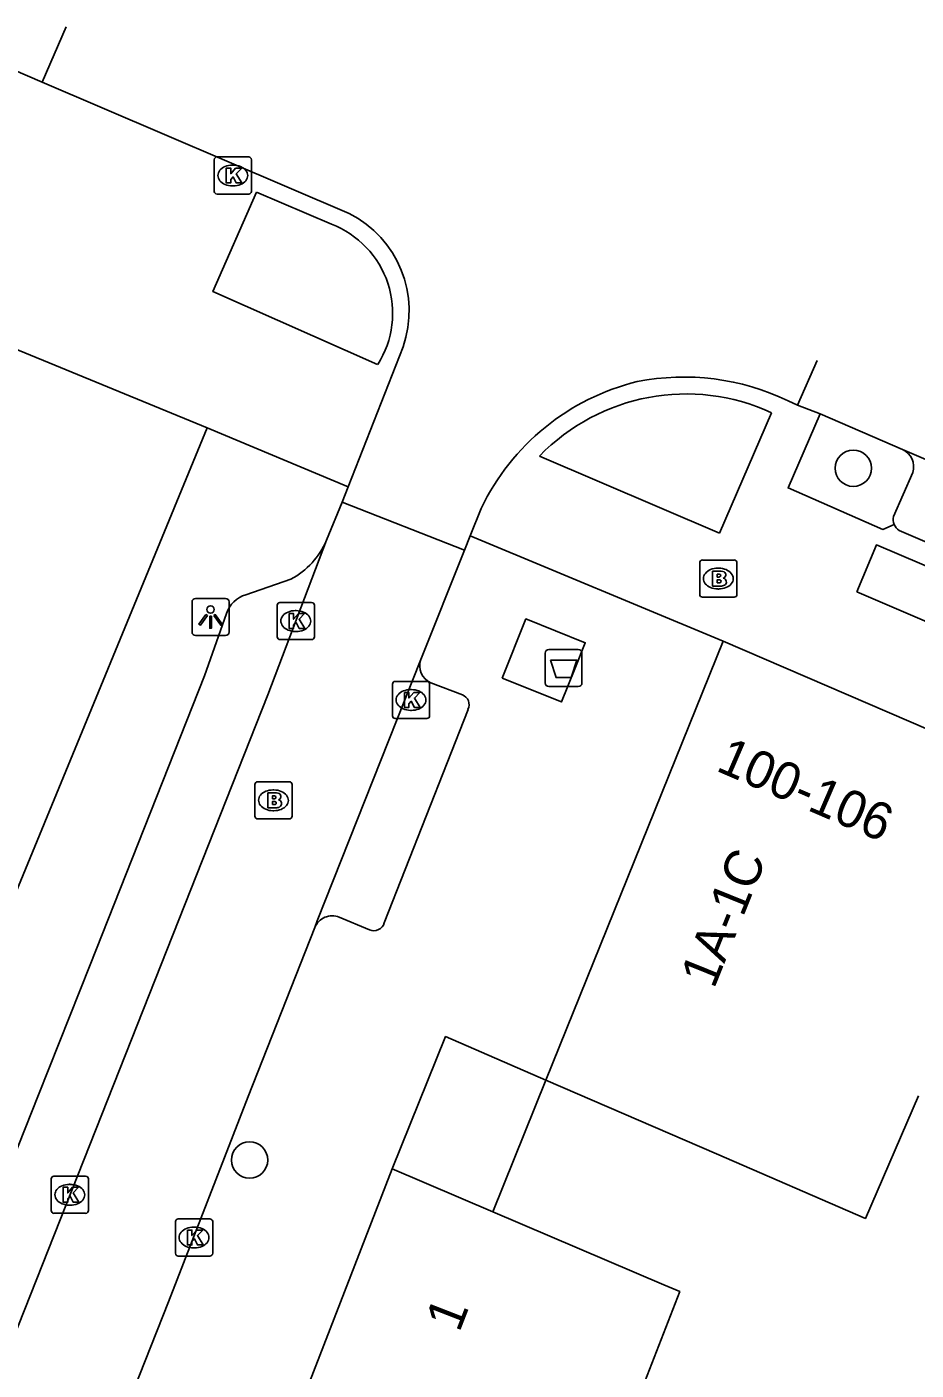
# Model space of a CAD drawing. Extents: x 161801 to 162379, y 382315 to 382832.
# Drawn here: x 162190.13 to 162214.04, y 382602.34 to 382638.48 of the extents above; entities that cross this region are included whole.
import ezdxf

# ---------------------------------------------------------------- set-up
doc = ezdxf.new("R2010")
doc.units = 0
for name, color, linetype in [('IMGEO_Afval_apart_plaats', 7, 'Continuous'), ('IMGEO_Boom', 7, 'Continuous'), ('IMGEO_Brandkraan', 7, 'Continuous'), ('IMGEO_Kolk', 7, 'Continuous'), ('IMGEO_Lichtpunt', 7, 'Continuous'), ('IMGEO_Pand', 7, 'Continuous'), ('IMGEO_Pand_nummerreeks', 7, 'Continuous'), ('IMGEO_Parkeervlak_open', 7, 'Continuous'), ('IMGEO_Rijbaan_lokaal_gesloten', 7, 'Continuous'), ('IMGEO_Rijbaan_lokaal_open', 7, 'Continuous'), ('IMGEO_Voetpad_gesloten', 7, 'Continuous'), ('IMGEO_Voetpad_open', 7, 'Continuous')]:
    doc.layers.add(name, color=color, linetype=linetype)

msp = doc.modelspace()

# ---------------------------------------------------------------- linework, layer by layer
at = {"layer": 'IMGEO_Afval_apart_plaats'}
for p, q in [((162204.167, 382621.733), (162204.957, 382621.733)), ((162204.957, 382621.733), (162204.167, 382621.733)), ((162204.067, 382620.833), (162204.067, 382621.633)), ((162204.067, 382621.633), (162204.067, 382620.833)), ((162205.057, 382621.633), (162205.057, 382620.833)), ((162205.057, 382620.833), (162205.057, 382621.633)), ((162204.957, 382620.733), (162204.167, 382620.733)), ((162204.167, 382620.733), (162204.957, 382620.733))]:
    msp.add_line(p, q, dxfattribs=at)
msp.add_lwpolyline([(162204.21, 382621.447), (162204.914, 382621.447), (162204.765, 382620.977), (162204.359, 382620.977), (162204.21, 382621.447)], dxfattribs=at)
for centre, start, end in [((162204.167, 382621.633), 90, 180), ((162204.167, 382621.633), 90, 180), ((162204.957, 382621.633), 0, 90), ((162204.957, 382621.633), 360, 90), ((162204.167, 382620.833), 180, 270), ((162204.167, 382620.833), 180, 270), ((162204.957, 382620.833), 270, 0), ((162204.957, 382620.833), 270, 0)]:
    msp.add_arc(centre, 0.1, start, end, dxfattribs=at)
at = {"layer": 'IMGEO_Boom'}
for centre in [(162212.353, 382626.609), (162196.117, 382607.996)]:
    msp.add_circle(centre, 0.489, dxfattribs=at)
at = {"layer": 'IMGEO_Brandkraan'}
for p, q in [((162208.222, 382623.213), (162208.222, 382624.065)), ((162208.297, 382624.139), (162209.149, 382624.139)), ((162208.71, 382623.919), (162208.735, 382623.919)), ((162209.223, 382624.065), (162209.223, 382623.213)), ((162208.733, 382623.359), (162208.708, 382623.359)), ((162209.149, 382623.139), (162208.297, 382623.139)), ((162196.334, 382618.174), (162197.186, 382618.174)), ((162196.259, 382617.248), (162196.259, 382618.1)), ((162196.747, 382617.954), (162196.772, 382617.954)), ((162197.26, 382618.1), (162197.26, 382617.248)), ((162196.77, 382617.394), (162196.745, 382617.394)), ((162197.186, 382617.174), (162196.334, 382617.174))]:
    msp.add_line(p, q, dxfattribs=at)
for points in [[(162208.222, 382623.213), (162208.222, 382624.065)], [(162208.297, 382624.139), (162209.149, 382624.139)], [(162209.223, 382624.065), (162209.223, 382623.213)], [(162208.57, 382623.839), (162208.57, 382623.439), (162208.783, 382623.439)], [(162208.801, 382623.839), (162208.57, 382623.839)], [(162208.749, 382623.758), (162208.695, 382623.758), (162208.695, 382623.682)], [(162208.695, 382623.682), (162208.748, 382623.682)], [(162208.757, 382623.606), (162208.695, 382623.606), (162208.695, 382623.525)], [(162208.695, 382623.525), (162208.757, 382623.525)], [(162209.149, 382623.139), (162208.297, 382623.139)], [(162196.334, 382618.174), (162197.186, 382618.174)], [(162196.259, 382617.248), (162196.259, 382618.1)], [(162196.607, 382617.874), (162196.607, 382617.474), (162196.82, 382617.474)], [(162196.838, 382617.874), (162196.607, 382617.874)], [(162196.786, 382617.793), (162196.732, 382617.793), (162196.732, 382617.717)], [(162197.26, 382618.1), (162197.26, 382617.248)], [(162196.732, 382617.717), (162196.785, 382617.717)], [(162196.794, 382617.641), (162196.732, 382617.641), (162196.732, 382617.56)], [(162196.732, 382617.56), (162196.794, 382617.56)], [(162197.186, 382617.174), (162196.334, 382617.174)]]:
    msp.add_lwpolyline(points, dxfattribs=at)
for centre, radius, start, end in [((162208.299, 382624.063), 0.0765, 91.552, 178.448), ((162208.299, 382624.063), 0.0765, 91.552, 178.448), ((162209.147, 382624.063), 0.0765, 1.552, 88.448), ((162209.147, 382624.063), 0.0765, 1.552, 88.448), ((162208.75, 382623.72), 0.0379, 267.8285, 90.9355), ((162208.758, 382623.565), 0.0404, 269.8759, 90.5077), ((162208.805, 382623.694), 0.145, 59.4692, 91.5367), ((162208.83, 382623.741), 0.0922, 285.5137, 58.1501), ((162208.835, 382623.549), 0.105, 301.3115, 78.989), ((162208.299, 382623.215), 0.0765, 181.552, 268.448), ((162208.299, 382623.215), 0.0765, 181.552, 268.448), ((162208.789, 382623.69), 0.251, 268.6676, 293.5347), ((162209.147, 382623.215), 0.0765, 271.552, 358.448), ((162209.147, 382623.215), 0.0765, 271.552, 358.448), ((162196.336, 382618.098), 0.0765, 91.552, 178.448), ((162196.336, 382618.098), 0.0765, 91.552, 178.448), ((162197.184, 382618.098), 0.0765, 1.552, 88.448), ((162197.184, 382618.098), 0.0765, 1.552, 88.448), ((162196.787, 382617.755), 0.0379, 267.8285, 90.9355), ((162196.842, 382617.729), 0.145, 59.4692, 91.5367), ((162196.867, 382617.776), 0.0922, 285.5137, 58.1501), ((162196.795, 382617.6), 0.0404, 269.8759, 90.5077), ((162196.826, 382617.725), 0.251, 268.6676, 293.5347), ((162196.872, 382617.584), 0.105, 301.3115, 78.989), ((162196.336, 382617.25), 0.0765, 181.552, 268.448), ((162196.336, 382617.25), 0.0765, 181.552, 268.448), ((162197.184, 382617.25), 0.0765, 271.552, 358.448), ((162197.184, 382617.25), 0.0765, 271.552, 358.448)]:
    msp.add_arc(centre, radius, start, end, dxfattribs=at)
for centre, major_axis, ratio, start_param, end_param in [((162208.709, 382623.639), (-0.387, 0.002), 0.722429, 4.712389, 7.853982), ((162208.734, 382623.639), (-0.39, 0.002), 0.717154, 1.570796, 4.712389), ((162196.746, 382617.674), (-0.387, 0.002), 0.722429, 4.712389, 7.853982), ((162196.771, 382617.674), (-0.39, 0.002), 0.717154, 1.570796, 4.712389)]:
    msp.add_ellipse(centre, major_axis=major_axis, ratio=ratio, start_param=start_param, end_param=end_param, dxfattribs=at)
at = {"layer": 'IMGEO_Kolk'}
for p, q in [((162195.167, 382634.056), (162195.167, 382634.908)), ((162195.242, 382634.982), (162196.094, 382634.982)), ((162195.655, 382634.762), (162195.68, 382634.762)), ((162196.168, 382634.908), (162196.168, 382634.056)), ((162195.678, 382634.202), (162195.653, 382634.202)), ((162196.094, 382633.982), (162195.242, 382633.982)), ((162196.859, 382622.071), (162196.859, 382622.923)), ((162196.934, 382622.997), (162197.786, 382622.997)), ((162197.86, 382622.923), (162197.86, 382622.071)), ((162197.347, 382622.777), (162197.372, 382622.777)), ((162197.37, 382622.217), (162197.345, 382622.217)), ((162197.786, 382621.997), (162196.934, 382621.997)), ((162199.959, 382619.948), (162199.959, 382620.8)), ((162200.034, 382620.874), (162200.886, 382620.874)), ((162200.447, 382620.654), (162200.472, 382620.654)), ((162200.96, 382620.8), (162200.96, 382619.948)), ((162200.47, 382620.094), (162200.445, 382620.094)), ((162200.886, 382619.874), (162200.034, 382619.874)), ((162190.782, 382606.637), (162190.782, 382607.489)), ((162190.857, 382607.563), (162191.709, 382607.563)), ((162191.27, 382607.343), (162191.295, 382607.343)), ((162191.783, 382607.489), (162191.783, 382606.637)), ((162191.709, 382606.563), (162190.857, 382606.563)), ((162191.293, 382606.783), (162191.268, 382606.783)), ((162194.124, 382605.487), (162194.124, 382606.339)), ((162194.199, 382606.413), (162195.051, 382606.413)), ((162194.612, 382606.193), (162194.637, 382606.193)), ((162195.125, 382606.339), (162195.125, 382605.487)), ((162194.635, 382605.633), (162194.61, 382605.633)), ((162195.051, 382605.413), (162194.199, 382605.413))]:
    msp.add_line(p, q, dxfattribs=at)
for points in [[(162195.167, 382634.056), (162195.167, 382634.908)], [(162195.242, 382634.982), (162196.094, 382634.982)], [(162196.168, 382634.908), (162196.168, 382634.056)], [(162195.488, 382634.682), (162195.611, 382634.682), (162195.611, 382634.531), (162195.741, 382634.682), (162195.905, 382634.682), (162195.759, 382634.531), (162195.912, 382634.282), (162195.76, 382634.282), (162195.675, 382634.446), (162195.611, 382634.379), (162195.611, 382634.282), (162195.488, 382634.282), (162195.488, 382634.682)], [(162196.094, 382633.982), (162195.242, 382633.982)], [(162196.859, 382622.071), (162196.859, 382622.923)], [(162196.934, 382622.997), (162197.786, 382622.997)], [(162197.86, 382622.923), (162197.86, 382622.071)], [(162197.18, 382622.697), (162197.303, 382622.697), (162197.303, 382622.546), (162197.433, 382622.697), (162197.597, 382622.697), (162197.451, 382622.546), (162197.604, 382622.297), (162197.452, 382622.297), (162197.367, 382622.461), (162197.303, 382622.394), (162197.303, 382622.297), (162197.18, 382622.297), (162197.18, 382622.697)], [(162197.786, 382621.997), (162196.934, 382621.997)], [(162199.959, 382619.948), (162199.959, 382620.8)], [(162200.034, 382620.874), (162200.886, 382620.874)], [(162200.96, 382620.8), (162200.96, 382619.948)], [(162200.28, 382620.574), (162200.403, 382620.574), (162200.403, 382620.423), (162200.533, 382620.574), (162200.697, 382620.574), (162200.551, 382620.423), (162200.704, 382620.174), (162200.552, 382620.174), (162200.467, 382620.338), (162200.403, 382620.271), (162200.403, 382620.174), (162200.28, 382620.174), (162200.28, 382620.574)], [(162200.886, 382619.874), (162200.034, 382619.874)], [(162190.782, 382606.637), (162190.782, 382607.489)], [(162190.857, 382607.563), (162191.709, 382607.563)], [(162191.103, 382607.263), (162191.226, 382607.263), (162191.226, 382607.112), (162191.356, 382607.263), (162191.52, 382607.263), (162191.374, 382607.112), (162191.527, 382606.863), (162191.375, 382606.863), (162191.29, 382607.027), (162191.226, 382606.96), (162191.226, 382606.863), (162191.103, 382606.863), (162191.103, 382607.263)], [(162191.783, 382607.489), (162191.783, 382606.637)], [(162191.709, 382606.563), (162190.857, 382606.563)], [(162194.124, 382605.487), (162194.124, 382606.339)], [(162194.199, 382606.413), (162195.051, 382606.413)], [(162195.125, 382606.339), (162195.125, 382605.487)], [(162194.445, 382606.113), (162194.568, 382606.113), (162194.568, 382605.962), (162194.698, 382606.113), (162194.862, 382606.113), (162194.716, 382605.962), (162194.869, 382605.713), (162194.717, 382605.713), (162194.632, 382605.877), (162194.568, 382605.81), (162194.568, 382605.713), (162194.445, 382605.713), (162194.445, 382606.113)], [(162195.051, 382605.413), (162194.199, 382605.413)]]:
    msp.add_lwpolyline(points, dxfattribs=at)
for centre, start, end in [((162195.244, 382634.906), 91.552, 178.448), ((162195.244, 382634.906), 91.552, 178.448), ((162196.092, 382634.906), 1.552, 88.448), ((162196.092, 382634.906), 1.552, 88.448), ((162195.244, 382634.058), 181.552, 268.448), ((162195.244, 382634.058), 181.552, 268.448), ((162196.092, 382634.058), 271.552, 358.448), ((162196.092, 382634.058), 271.552, 358.448), ((162196.936, 382622.921), 91.552, 178.448), ((162196.936, 382622.921), 91.552, 178.448), ((162197.784, 382622.921), 1.552, 88.448), ((162197.784, 382622.921), 1.552, 88.448), ((162196.936, 382622.073), 181.552, 268.448), ((162196.936, 382622.073), 181.552, 268.448), ((162197.784, 382622.073), 271.552, 358.448), ((162197.784, 382622.073), 271.552, 358.448), ((162200.036, 382620.798), 91.552, 178.448), ((162200.036, 382620.798), 91.552, 178.448), ((162200.884, 382620.798), 1.552, 88.448), ((162200.884, 382620.798), 1.552, 88.448), ((162200.036, 382619.95), 181.552, 268.448), ((162200.036, 382619.95), 181.552, 268.448), ((162200.884, 382619.95), 271.552, 358.448), ((162200.884, 382619.95), 271.552, 358.448), ((162190.859, 382607.487), 91.552, 178.448), ((162190.859, 382607.487), 91.552, 178.448), ((162191.707, 382607.487), 1.552, 88.448), ((162191.707, 382607.487), 1.552, 88.448), ((162190.859, 382606.639), 181.552, 268.448), ((162190.859, 382606.639), 181.552, 268.448), ((162191.707, 382606.639), 271.552, 358.448), ((162191.707, 382606.639), 271.552, 358.448), ((162194.201, 382606.337), 91.552, 178.448), ((162194.201, 382606.337), 91.552, 178.448), ((162195.049, 382606.337), 1.552, 88.448), ((162195.049, 382606.337), 1.552, 88.448), ((162194.201, 382605.489), 181.552, 268.448), ((162194.201, 382605.489), 181.552, 268.448), ((162195.049, 382605.489), 271.552, 358.448), ((162195.049, 382605.489), 271.552, 358.448)]:
    msp.add_arc(centre, 0.0765, start, end, dxfattribs=at)
for centre, major_axis, ratio, start_param, end_param in [((162195.654, 382634.482), (-0.387, 0.002), 0.722429, 4.712389, 7.853982), ((162195.679, 382634.482), (-0.39, 0.002), 0.717154, 1.570796, 4.712389), ((162197.346, 382622.497), (-0.387, 0.002), 0.722429, 4.712389, 7.853982), ((162197.371, 382622.497), (-0.39, 0.002), 0.717154, 1.570796, 4.712389), ((162200.446, 382620.374), (-0.387, 0.002), 0.722429, 4.712389, 7.853982), ((162200.471, 382620.374), (-0.39, 0.002), 0.717154, 1.570796, 4.712389), ((162191.269, 382607.063), (-0.387, 0.002), 0.722429, 4.712389, 7.853982), ((162191.294, 382607.063), (-0.39, 0.002), 0.717154, 1.570796, 4.712389), ((162194.611, 382605.913), (-0.387, 0.002), 0.722429, 4.712389, 7.853982), ((162194.636, 382605.913), (-0.39, 0.002), 0.717154, 1.570796, 4.712389)]:
    msp.add_ellipse(centre, major_axis=major_axis, ratio=ratio, start_param=start_param, end_param=end_param, dxfattribs=at)
at = {"layer": 'IMGEO_Lichtpunt'}
for p, q in [((162194.57, 382623.01), (162194.57, 382622.203)), ((162194.57, 382623.01), (162194.57, 382622.203)), ((162195.472, 382623.105), (162194.664, 382623.105)), ((162195.472, 382623.105), (162194.664, 382623.105)), ((162195.566, 382622.203), (162195.566, 382623.01)), ((162195.566, 382622.203), (162195.566, 382623.01)), ((162194.664, 382622.109), (162195.472, 382622.109)), ((162194.664, 382622.109), (162195.472, 382622.109))]:
    msp.add_line(p, q, dxfattribs=at)
for points in [[(162194.944, 382622.674), (162194.983, 382622.646), (162194.795, 382622.384), (162194.757, 382622.411), (162194.944, 382622.674)], [(162195.046, 382622.626), (162195.093, 382622.626), (162195.093, 382622.304), (162195.046, 382622.304), (162195.046, 382622.626)], [(162195.156, 382622.646), (162195.194, 382622.673), (162195.381, 382622.411), (162195.342, 382622.383), (162195.156, 382622.646)]]:
    msp.add_lwpolyline(points, dxfattribs=at)
msp.add_circle((162195.069, 382622.808), 0.0994, dxfattribs=at)
for centre, start, end in [((162194.664, 382623.01), 90, 180), ((162194.664, 382623.01), 90, 180), ((162195.472, 382623.01), 0, 90), ((162195.472, 382623.01), 0, 90), ((162194.664, 382622.203), 180, 270), ((162194.664, 382622.203), 180, 270), ((162195.472, 382622.203), 270, 0), ((162195.472, 382622.203), 270, 360)]:
    msp.add_arc(centre, 0.0946, start, end, dxfattribs=at)
at = {"layer": 'IMGEO_Pand'}
for points in [[(162170.563, 382637.65), (162182.876, 382632.633), (162184.555, 382631.986), (162194.979, 382627.699)], [(162194.979, 382627.699), (162189.718, 382614.907)], [(162204.087, 382610.149), (162208.854, 382621.959)], [(162208.854, 382621.959), (162217.734, 382618.126)], [(162214.108, 382609.725), (162212.678, 382606.426), (162208.675, 382608.161), (162204.087, 382610.149)], [(162197.557, 382601.585), (162199.956, 382607.761)], [(162202.657, 382606.606), (162199.956, 382607.761)], [(162202.657, 382606.606), (162207.255, 382604.641), (162207.687, 382604.456), (162206.561, 382601.558), (162211.748, 382599.543), (162210.577, 382596.529)]]:
    msp.add_lwpolyline(points, dxfattribs=at)
at = {"layer": 'IMGEO_Parkeervlak_open'}
msp.add_lwpolyline([(162213.955, 382626.493), (162213.438, 382625.31)], dxfattribs=at)
for centre, radius, start, end in [((162213.46, 382626.643), 0.517, 343.1113, 64.951), ((162213.753, 382625.22), 0.328, 164.1118, 202.3072)]:
    msp.add_arc(centre, radius, start, end, dxfattribs=at)
at = {"layer": 'IMGEO_Rijbaan_lokaal_gesloten'}
for points in [[(162190.539, 382636.999), (162191.188, 382638.482)], [(162187.705, 382638.215), (162190.539, 382636.999)], [(162211.378, 382629.505), (162210.854, 382628.309)], [(162210.854, 382628.309), (162211.464, 382628.073)], [(162211.464, 382628.073), (162213.679, 382627.112)], [(162213.679, 382627.112), (162235.739, 382617.639)]]:
    msp.add_lwpolyline(points, dxfattribs=at)
at = {"layer": 'IMGEO_Rijbaan_lokaal_open'}
for points in [[(162190.539, 382636.999), (162198.797, 382633.462)], [(162200.244, 382629.872), (162198.772, 382626.104)], [(162210.6, 382628.425), (162210.854, 382628.309)], [(162198.772, 382626.104), (162198.611, 382625.691)], [(162198.611, 382625.691), (162198.183, 382624.669)], [(162198.611, 382625.691), (162201.9, 382624.403)], [(162202.052, 382624.786), (162202.347, 382625.528)], [(162198.183, 382624.669), (162196.606, 382620.511), (162183.036, 382586.209)], [(162201.9, 382624.403), (162202.052, 382624.786)], [(162200.724, 382621.462), (162201.9, 382624.403)], [(162197.87, 382614.249), (162197.933, 382614.428), (162200.724, 382621.462)], [(162184.773, 382581.075), (162192.527, 382600.624), (162193.938, 382604.183), (162196.082, 382609.705), (162197.87, 382614.249)]]:
    msp.add_lwpolyline(points, dxfattribs=at)
for centre, radius, start, end in [((162197.471, 382630.841), 2.937, 340.7366, 63.1686), ((162207.801, 382622.585), 6.476, 64.3891, 101.1975), ((162208.05, 382622.798), 6.323, 103.7854, 154.4146)]:
    msp.add_arc(centre, radius, start, end, dxfattribs=at)
at = {"layer": 'IMGEO_Voetpad_gesloten'}
msp.add_lwpolyline([(162202.912, 382620.961), (162203.549, 382622.553), (162205.146, 382621.914), (162204.866, 382621.215), (162204.509, 382620.322), (162202.912, 382620.961)], dxfattribs=at)
at = {"layer": 'IMGEO_Voetpad_open'}
for points in [[(162199.562, 382629.403), (162195.132, 382631.359), (162196.304, 382634.039)], [(162196.304, 382634.039), (162198.318, 382633.171)], [(162210.155, 382628.1), (162208.759, 382624.859)], [(162213.45, 382625.096), (162213.146, 382624.96), (162210.601, 382626.08), (162211.464, 382628.073)], [(162198.772, 382626.104), (162194.979, 382627.699)], [(162208.759, 382624.859), (162203.917, 382626.936)], [(162208.854, 382621.959), (162202.052, 382624.786)], [(162234.242, 382616.077), (162230.532, 382617.668), (162213.588, 382624.937)], [(162212.448, 382623.284), (162212.974, 382624.543), (162223.092, 382620.232), (162222.519, 382618.968), (162212.448, 382623.284)], [(162196.018, 382623.203), (162197.228, 382623.627)], [(162182.318, 382589.26), (162190.44, 382609.748), (162191.828, 382613.249), (162194.908, 382621.019), (162195.498, 382622.698)], [(162201.84, 382620.509), (162200.994, 382620.833)], [(162199.741, 382614.377), (162201.992, 382620.121)], [(162198.531, 382614.528), (162199.342, 382614.191)], [(162199.956, 382607.761), (162201.387, 382611.319), (162204.087, 382610.149)], [(162204.087, 382610.149), (162202.657, 382606.606)]]:
    msp.add_lwpolyline(points, dxfattribs=at)
for centre, radius, start, end in [((162197.407, 382630.781), 2.558, 327.4122, 69.129), ((162207.856, 382623.123), 5.483, 65.2094, 135.9301), ((162213.754, 382625.22), 0.328, 202.2309, 239.6802), ((162196.275, 382625.459), 2.065, 297.4766, 337.5124), ((162196.23, 382622.465), 0.768, 106.0083, 162.3149), ((162201.19, 382621.29), 0.497, 159.6792, 246.784), ((162201.741, 382620.247), 0.28, 333.4005, 69.3853), ((162198.339, 382614.06), 0.506, 67.7081, 158.06), ((162199.46, 382614.46), 0.293, 246.3712, 343.6154)]:
    msp.add_arc(centre, radius, start, end, dxfattribs=at)

# ---------------------------------------------------------------- texts
at = {"layer": 'IMGEO_Pand_nummerreeks'}
for s, rotation, p in [('100-106', 336.6521, (162208.628, 382618.484)), ('1A-1C', 68.019, (162208.605, 382612.579)), ('1', 68.768, (162201.755, 382603.335))]:
    msp.add_text(s, height=1, rotation=rotation, dxfattribs=at).set_placement(p)

doc.saveas('drawing.dxf')
